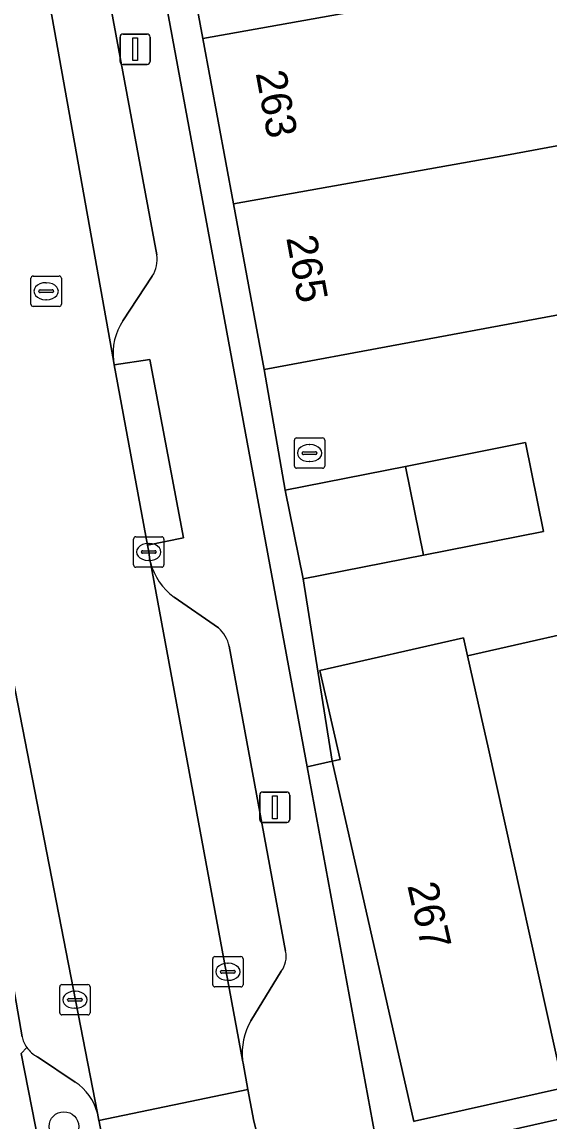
# Model space of a CAD drawing. Extents: x 160377 to 161131, y 383938 to 384853.
# Drawn here: x 160815.54 to 160832.91, y 384537.03 to 384573.2 of the extents above; entities that cross this region are included whole.
import ezdxf

# ---------------------------------------------------------------- set-up
doc = ezdxf.new("R2010")
doc.units = 0
for name, color, linetype in [('IMGEO_Boom', 7, 'Continuous'), ('IMGEO_Erf', 7, 'Continuous'), ('IMGEO_Groenvoorziening', 7, 'Continuous'), ('IMGEO_Kolk', 7, 'Continuous'), ('IMGEO_Lichtmast', 7, 'Continuous'), ('IMGEO_Muur', 7, 'Continuous'), ('IMGEO_Pand', 7, 'Continuous'), ('IMGEO_Pand_nummerreeks', 7, 'Continuous'), ('IMGEO_Parkeervlak_open', 7, 'Continuous'), ('IMGEO_Rijbaan_lokaal_open', 7, 'Continuous'), ('IMGEO_Rioolput', 7, 'Continuous'), ('IMGEO_Voetpad_open', 7, 'Continuous')]:
    doc.layers.add(name, color=color, linetype=linetype)

msp = doc.modelspace()

# ---------------------------------------------------------------- linework, layer by layer
at = {"layer": 'IMGEO_Boom'}
msp.add_circle((160816.923, 384536.878), 0.489, dxfattribs=at)
at = {"layer": 'IMGEO_Erf'}
for points in [[(160836.079, 384564.109), (160832.472, 384563.442), (160823.508, 384561.776), (160824.197, 384557.807), (160828.153, 384558.589), (160832.1, 384559.368), (160832.697, 384556.45), (160828.75, 384555.671), (160824.794, 384554.889), (160825.745, 384548.894), (160824.919, 384548.707), (160827.304, 384535.796), (160828.384, 384536.039), (160877.181, 384547.027)], [(160833.346, 384538.155), (160828.447, 384537.052), (160828.43, 384537.048), (160825.745, 384548.894), (160826.001, 384548.952), (160825.337, 384551.881), (160830.056, 384552.951), (160830.191, 384552.359), (160835.314, 384553.515)]]:
    msp.add_lwpolyline(points, dxfattribs=at)
at = {"layer": 'IMGEO_Groenvoorziening'}
for points in [[(160815.7, 384539.483), (160815.52, 384539.282), (160816.219, 384535.713), (160818.259, 384536.105), (160818.077, 384537.048), (160818.072, 384537.074), (160818.024, 384537.321)], [(160817.288, 384538.344), (160816.055, 384539.17)]]:
    msp.add_lwpolyline(points, dxfattribs=at)
for centre, radius, start, end in [((160816.519, 384540.054), 0.998, 214.8819, 242.3135), ((160816.274, 384536.838), 1.816, 15.4246, 56.0419)]:
    msp.add_arc(centre, radius, start, end, dxfattribs=at)
at = {"layer": 'IMGEO_Kolk'}
for p, q in [((160819.211, 384555.347), (160819.211, 384556.199)), ((160819.286, 384556.273), (160820.138, 384556.273)), ((160820.212, 384556.199), (160820.212, 384555.347)), ((160819.47, 384555.767), (160819.47, 384555.779)), ((160819.513, 384555.816), (160819.911, 384555.816)), ((160819.699, 384556.053), (160819.724, 384556.053)), ((160819.954, 384555.779), (160819.954, 384555.767)), ((160819.908, 384555.73), (160819.51, 384555.73)), ((160819.722, 384555.493), (160819.697, 384555.493)), ((160820.138, 384555.273), (160819.286, 384555.273)), ((160821.814, 384541.543), (160821.814, 384542.395)), ((160821.889, 384542.469), (160822.741, 384542.469)), ((160822.815, 384542.395), (160822.815, 384541.543)), ((160822.116, 384542.012), (160822.514, 384542.012)), ((160822.302, 384542.249), (160822.327, 384542.249)), ((160822.073, 384541.963), (160822.073, 384541.975)), ((160822.511, 384541.926), (160822.113, 384541.926)), ((160822.325, 384541.689), (160822.3, 384541.689)), ((160822.557, 384541.975), (160822.557, 384541.963)), ((160816.784, 384540.623), (160816.784, 384541.475)), ((160816.859, 384541.549), (160817.711, 384541.549)), ((160817.272, 384541.329), (160817.297, 384541.329)), ((160817.785, 384541.475), (160817.785, 384540.623)), ((160822.741, 384541.469), (160821.889, 384541.469)), ((160817.043, 384541.043), (160817.043, 384541.055)), ((160817.481, 384541.006), (160817.083, 384541.006)), ((160817.086, 384541.092), (160817.484, 384541.092)), ((160817.527, 384541.055), (160817.527, 384541.043)), ((160817.295, 384540.769), (160817.27, 384540.769)), ((160817.711, 384540.549), (160816.859, 384540.549))]:
    msp.add_line(p, q, dxfattribs=at)
for points in [[(160819.211, 384555.347), (160819.211, 384556.199)], [(160819.286, 384556.273), (160820.138, 384556.273)], [(160820.212, 384556.199), (160820.212, 384555.347)], [(160820.138, 384555.273), (160819.286, 384555.273)], [(160821.814, 384541.543), (160821.814, 384542.395)], [(160821.889, 384542.469), (160822.741, 384542.469)], [(160822.815, 384542.395), (160822.815, 384541.543)], [(160816.784, 384540.623), (160816.784, 384541.475)], [(160816.859, 384541.549), (160817.711, 384541.549)], [(160817.785, 384541.475), (160817.785, 384540.623)], [(160822.741, 384541.469), (160821.889, 384541.469)], [(160817.711, 384540.549), (160816.859, 384540.549)]]:
    msp.add_lwpolyline(points, dxfattribs=at)
for centre, radius, start, end in [((160819.288, 384556.197), 0.0765, 91.552, 178.448), ((160819.288, 384556.197), 0.0765, 91.552, 178.448), ((160820.136, 384556.197), 0.0765, 1.552, 88.448), ((160820.136, 384556.197), 0.0765, 1.552, 88.448), ((160819.51, 384555.776), 0.0403, 85.8775, 175.7526), ((160819.507, 384555.766), 0.0366, 178.938, 274.7102), ((160819.911, 384555.773), 0.043, 264.8664, 352.4533), ((160819.915, 384555.778), 0.0386, 1.7309, 96.639), ((160819.288, 384555.349), 0.0765, 181.552, 268.448), ((160819.288, 384555.349), 0.0765, 181.552, 268.448), ((160820.136, 384555.349), 0.0765, 271.552, 358.448), ((160820.136, 384555.349), 0.0765, 271.552, 358.448), ((160821.891, 384542.393), 0.0765, 91.552, 178.448), ((160821.891, 384542.393), 0.0765, 91.552, 178.448), ((160822.739, 384542.393), 0.0765, 1.552, 88.448), ((160822.739, 384542.393), 0.0765, 1.552, 88.448), ((160822.113, 384541.972), 0.0403, 85.8775, 175.7526), ((160822.518, 384541.974), 0.0386, 1.7309, 96.639), ((160822.11, 384541.962), 0.0366, 178.938, 274.7102), ((160822.514, 384541.969), 0.043, 264.8664, 352.4533), ((160816.861, 384541.473), 0.0765, 91.552, 178.448), ((160816.861, 384541.473), 0.0765, 91.552, 178.448), ((160817.709, 384541.473), 0.0765, 1.552, 88.448), ((160817.709, 384541.473), 0.0765, 1.552, 88.448), ((160821.891, 384541.545), 0.0765, 181.552, 268.448), ((160821.891, 384541.545), 0.0765, 181.552, 268.448), ((160822.739, 384541.545), 0.0765, 271.552, 358.448), ((160822.739, 384541.545), 0.0765, 271.552, 358.448), ((160817.083, 384541.052), 0.0403, 85.8775, 175.7526), ((160817.08, 384541.042), 0.0366, 178.938, 274.7102), ((160817.484, 384541.049), 0.043, 264.8664, 352.4533), ((160817.488, 384541.054), 0.0386, 1.7309, 96.639), ((160816.861, 384540.625), 0.0765, 181.552, 268.448), ((160816.861, 384540.625), 0.0765, 181.552, 268.448), ((160817.709, 384540.625), 0.0765, 271.552, 358.448), ((160817.709, 384540.625), 0.0765, 271.552, 358.448)]:
    msp.add_arc(centre, radius, start, end, dxfattribs=at)
for centre, major_axis, ratio, start_param, end_param in [((160819.698, 384555.773), (-0.387, 0.002), 0.722429, 4.712389, 7.853982), ((160819.723, 384555.773), (-0.39, 0.002), 0.717154, 1.570796, 4.712389), ((160822.301, 384541.969), (-0.387, 0.002), 0.722429, 4.712389, 7.853982), ((160822.326, 384541.969), (-0.39, 0.002), 0.717154, 1.570796, 4.712389), ((160817.271, 384541.049), (-0.387, 0.002), 0.722429, 4.712389, 7.853982), ((160817.296, 384541.049), (-0.39, 0.002), 0.717154, 1.570796, 4.712389)]:
    msp.add_ellipse(centre, major_axis=major_axis, ratio=ratio, start_param=start_param, end_param=end_param, dxfattribs=at)
at = {"layer": 'IMGEO_Lichtmast'}
for p, q in [((160818.867, 384572.805), (160819.657, 384572.805)), ((160819.657, 384572.805), (160818.867, 384572.805)), ((160818.767, 384571.905), (160818.767, 384572.705)), ((160818.767, 384572.705), (160818.767, 384571.905)), ((160819.757, 384572.705), (160819.757, 384571.905)), ((160819.757, 384571.905), (160819.757, 384572.705)), ((160819.657, 384571.805), (160818.867, 384571.805)), ((160818.867, 384571.805), (160819.657, 384571.805)), ((160823.459, 384547.878), (160824.249, 384547.878)), ((160824.249, 384547.878), (160823.459, 384547.878)), ((160823.359, 384546.978), (160823.359, 384547.778)), ((160823.359, 384547.778), (160823.359, 384546.978)), ((160824.349, 384547.778), (160824.349, 384546.978)), ((160824.349, 384546.978), (160824.349, 384547.778)), ((160824.249, 384546.878), (160823.459, 384546.878)), ((160823.459, 384546.878), (160824.249, 384546.878))]:
    msp.add_line(p, q, dxfattribs=at)
for points in [[(160819.187, 384572.68), (160819.337, 384572.68), (160819.337, 384571.93), (160819.187, 384571.93), (160819.187, 384572.68)], [(160823.779, 384547.753), (160823.929, 384547.753), (160823.929, 384547.003), (160823.779, 384547.003), (160823.779, 384547.753)]]:
    msp.add_lwpolyline(points, dxfattribs=at)
for centre, start, end in [((160818.867, 384572.705), 90, 180), ((160818.867, 384572.705), 90, 180), ((160819.657, 384572.705), 0, 90), ((160819.657, 384572.705), 360, 90), ((160818.867, 384571.905), 180, 270), ((160818.867, 384571.905), 180, 270), ((160819.657, 384571.905), 270, 0), ((160819.657, 384571.905), 270, 0), ((160823.459, 384547.778), 90, 180), ((160823.459, 384547.778), 90, 180), ((160824.249, 384547.778), 0, 90), ((160824.249, 384547.778), 360, 90), ((160823.459, 384546.978), 180, 270), ((160823.459, 384546.978), 180, 270), ((160824.249, 384546.978), 270, 0), ((160824.249, 384546.978), 270, 0)]:
    msp.add_arc(centre, 0.1, start, end, dxfattribs=at)
at = {"layer": 'IMGEO_Muur'}
msp.add_lwpolyline([(160825.745, 384548.894), (160824.794, 384554.889)], dxfattribs=at)
at = {"layer": 'IMGEO_Pand'}
for points in [[(160829.466, 384579.707), (160820.48, 384578.095), (160821.489, 384572.655), (160830.472, 384574.267), (160834.079, 384574.933), (160833.073, 384580.374)], [(160834.079, 384574.933), (160830.472, 384574.267), (160821.489, 384572.655), (160822.498, 384567.216), (160831.477, 384568.826), (160835.084, 384569.493)], [(160835.084, 384569.493), (160831.477, 384568.826), (160822.498, 384567.216), (160823.508, 384561.776), (160832.472, 384563.442), (160836.079, 384564.109)], [(160832.1, 384559.368), (160828.153, 384558.589), (160828.75, 384555.671), (160832.697, 384556.45)], [(160828.153, 384558.589), (160824.197, 384557.807), (160824.794, 384554.889), (160828.75, 384555.671)], [(160835.981, 384550.558), (160835.314, 384553.515), (160830.191, 384552.359), (160830.718, 384550.022), (160830.858, 384549.402), (160833.346, 384538.155), (160838.47, 384539.309)], [(160830.858, 384549.402), (160830.718, 384550.022), (160830.191, 384552.359), (160830.056, 384552.951), (160825.337, 384551.881), (160826.001, 384548.952), (160825.745, 384548.894), (160828.43, 384537.048), (160828.447, 384537.052), (160833.346, 384538.155)]]:
    msp.add_lwpolyline(points, close=True, dxfattribs=at)
at = {"layer": 'IMGEO_Parkeervlak_open'}
for points in [[(160818.024, 384537.321), (160808.395, 384586.778)], [(160814.28, 384585.825), (160814.64, 384583.89), (160818.551, 384562.065)], [(160807.162, 384583.224), (160808.442, 384576.668), (160809.961, 384576.919), (160810.2, 384575.304), (160808.747, 384575.103), (160810.749, 384564.848), (160812.277, 384565.101), (160812.623, 384563.321), (160811.098, 384563.058), (160813.217, 384552.203), (160814.725, 384552.401), (160814.98, 384550.736), (160813.547, 384550.512), (160814.928, 384543.438), (160815.544, 384539.832)], [(160819.973, 384565.541), (160816.904, 384582.075)], [(160818.864, 384563.369), (160819.829, 384564.845)], [(160819.766, 384555.429), (160822.798, 384539.063)], [(160822, 384553.274), (160820.548, 384554.291)], [(160824.212, 384542.646), (160822.361, 384552.671)], [(160823.067, 384540.361), (160824.07, 384541.984)], [(160816.055, 384539.17), (160817.288, 384538.344)]]:
    msp.add_lwpolyline(points, dxfattribs=at)
for centre, radius, start, end in [((160818.988, 384565.382), 0.998, 327.4479, 9.1734), ((160820.446, 384562.3), 1.909, 145.94, 187.0652), ((160821.746, 384555.952), 2.048, 194.7949, 234.1965), ((160821.277, 384552.432), 1.11, 12.4456, 49.3701), ((160823.407, 384542.472), 0.823, 323.611, 12.1759), ((160824.908, 384539.303), 2.123, 150.1032, 186.4801), ((160816.511, 384540.055), 0.992, 192.9797, 215.1888), ((160816.519, 384540.054), 0.998, 214.8819, 242.3135), ((160816.274, 384536.838), 1.816, 15.4246, 56.0419)]:
    msp.add_arc(centre, radius, start, end, dxfattribs=at)
at = {"layer": 'IMGEO_Rijbaan_lokaal_open'}
for points in [[(160808.366, 384586.942), (160808.395, 384586.778), (160818.024, 384537.321), (160818.072, 384537.074), (160822.974, 384538.097), (160822.812, 384538.963), (160822.804, 384539.013), (160822.798, 384539.063), (160819.766, 384555.429), (160819.757, 384555.467), (160819.748, 384555.505), (160819.712, 384555.773), (160819.668, 384555.994), (160818.573, 384561.931), (160818.551, 384562.065), (160814.64, 384583.89)], [(160823.391, 384536.192), (160823.17, 384537.054), (160822.974, 384538.097), (160818.072, 384537.074), (160818.077, 384537.048), (160818.259, 384536.105), (160818.27, 384536.051), (160818.393, 384535.428)]]:
    msp.add_lwpolyline(points, dxfattribs=at)
at = {"layer": 'IMGEO_Rioolput'}
for p, q in [((160815.913, 384564.848), (160816.765, 384564.848)), ((160815.838, 384563.922), (160815.838, 384564.774)), ((160816.326, 384564.628), (160816.351, 384564.628)), ((160816.839, 384564.774), (160816.839, 384563.922)), ((160816.097, 384564.342), (160816.097, 384564.354)), ((160816.535, 384564.305), (160816.137, 384564.305)), ((160816.14, 384564.391), (160816.538, 384564.391)), ((160816.581, 384564.354), (160816.581, 384564.342)), ((160816.765, 384563.848), (160815.913, 384563.848)), ((160816.349, 384564.068), (160816.324, 384564.068)), ((160824.499, 384558.599), (160824.499, 384559.451)), ((160824.574, 384559.525), (160825.426, 384559.525)), ((160825.5, 384559.451), (160825.5, 384558.599)), ((160824.758, 384559.019), (160824.758, 384559.031)), ((160824.801, 384559.068), (160825.199, 384559.068)), ((160824.987, 384559.305), (160825.012, 384559.305)), ((160825.242, 384559.031), (160825.242, 384559.019)), ((160825.196, 384558.982), (160824.798, 384558.982)), ((160825.01, 384558.745), (160824.985, 384558.745)), ((160825.426, 384558.525), (160824.574, 384558.525))]:
    msp.add_line(p, q, dxfattribs=at)
for points in [[(160815.913, 384564.848), (160816.765, 384564.848)], [(160815.838, 384563.922), (160815.838, 384564.774)], [(160816.839, 384564.774), (160816.839, 384563.922)], [(160816.765, 384563.848), (160815.913, 384563.848)], [(160824.499, 384558.599), (160824.499, 384559.451)], [(160824.574, 384559.525), (160825.426, 384559.525)], [(160825.5, 384559.451), (160825.5, 384558.599)], [(160825.426, 384558.525), (160824.574, 384558.525)]]:
    msp.add_lwpolyline(points, dxfattribs=at)
for centre, radius, start, end in [((160815.915, 384564.772), 0.0765, 91.552, 178.448), ((160815.915, 384564.772), 0.0765, 91.552, 178.448), ((160816.763, 384564.772), 0.0765, 1.552, 88.448), ((160816.763, 384564.772), 0.0765, 1.552, 88.448), ((160816.137, 384564.351), 0.0403, 85.8775, 175.7526), ((160816.134, 384564.341), 0.0366, 178.938, 274.7102), ((160816.538, 384564.348), 0.043, 264.8664, 352.4533), ((160816.542, 384564.353), 0.0386, 1.7309, 96.639), ((160815.915, 384563.924), 0.0765, 181.552, 268.448), ((160815.915, 384563.924), 0.0765, 181.552, 268.448), ((160816.763, 384563.924), 0.0765, 271.552, 358.448), ((160816.763, 384563.924), 0.0765, 271.552, 358.448), ((160824.576, 384559.449), 0.0765, 91.552, 178.448), ((160824.576, 384559.449), 0.0765, 91.552, 178.448), ((160825.424, 384559.449), 0.0765, 1.552, 88.448), ((160825.424, 384559.449), 0.0765, 1.552, 88.448), ((160824.798, 384559.028), 0.0403, 85.8775, 175.7526), ((160824.795, 384559.018), 0.0366, 178.938, 274.7102), ((160825.199, 384559.025), 0.043, 264.8664, 352.4533), ((160825.203, 384559.03), 0.0386, 1.7309, 96.639), ((160824.576, 384558.601), 0.0765, 181.552, 268.448), ((160824.576, 384558.601), 0.0765, 181.552, 268.448), ((160825.424, 384558.601), 0.0765, 271.552, 358.448), ((160825.424, 384558.601), 0.0765, 271.552, 358.448)]:
    msp.add_arc(centre, radius, start, end, dxfattribs=at)
for centre, major_axis, ratio, start_param, end_param in [((160816.325, 384564.348), (-0.387, 0.002), 0.722429, 4.712389, 7.853982), ((160816.35, 384564.348), (-0.39, 0.002), 0.717154, 1.570796, 4.712389), ((160824.986, 384559.025), (-0.387, 0.002), 0.722429, 4.712389, 7.853982), ((160825.011, 384559.025), (-0.39, 0.002), 0.717154, 1.570796, 4.712389)]:
    msp.add_ellipse(centre, major_axis=major_axis, ratio=ratio, start_param=start_param, end_param=end_param, dxfattribs=at)
at = {"layer": 'IMGEO_Voetpad_open'}
for points in [[(160750.44, 384669.667), (160816.984, 384591.607), (160818.812, 384581.761), (160824.919, 384548.707), (160825.745, 384548.894), (160824.794, 384554.889), (160824.197, 384557.807), (160823.508, 384561.776), (160822.498, 384567.216), (160821.489, 384572.655), (160820.48, 384578.095), (160819.47, 384583.535), (160818.461, 384588.975), (160817.887, 384592.065), (160816.799, 384593.342), (160813.196, 384597.57), (160809.528, 384601.874), (160805.909, 384606.122), (160802.399, 384610.25), (160798.948, 384614.297), (160795.497, 384618.345)], [(160745.948, 384658.713), (160745.656, 384658.636), (160741.646, 384663.363), (160743.2, 384664.676), (160741.8, 384666.319), (160738.611, 384663.488), (160752.089, 384647.71), (160753.096, 384646.531), (160756.612, 384642.415), (160759.221, 384639.361), (160784.593, 384609.659), (160785.555, 384608.533), (160801.827, 384589.484), (160804.227, 384586.696), (160805.221, 384581.626), (160814.707, 384533.039), (160818.393, 384535.428), (160818.27, 384536.051), (160818.259, 384536.105), (160816.219, 384535.713), (160815.52, 384539.282), (160815.7, 384539.483)], [(160816.147, 384586.236), (160816.904, 384582.075), (160819.973, 384565.541)], [(160815.544, 384539.832), (160814.928, 384543.438), (160813.547, 384550.512), (160813.217, 384552.203), (160811.098, 384563.058), (160810.749, 384564.848), (160808.747, 384575.103), (160808.442, 384576.668), (160807.162, 384583.224)], [(160822.798, 384539.063), (160822.804, 384539.013), (160822.812, 384538.963), (160822.974, 384538.097), (160823.17, 384537.054), (160823.391, 384536.192), (160827.304, 384535.796), (160824.919, 384548.707), (160818.812, 384581.761)], [(160819.829, 384564.845), (160818.864, 384563.369)], [(160818.551, 384562.065), (160818.573, 384561.931), (160819.747, 384562.108), (160820.851, 384556.238), (160819.668, 384555.994), (160819.712, 384555.773), (160819.748, 384555.505), (160819.757, 384555.467), (160819.766, 384555.429)], [(160935.073, 384557.207), (160934.119, 384558.397), (160932.131, 384556.814), (160932.313, 384556.509), (160931.962, 384556.425), (160931.143, 384557.427), (160925.7, 384555.846), (160923.778, 384555.265), (160920.05, 384554.138), (160919.688, 384554.028), (160916.6, 384553.146), (160916.499, 384553.113), (160909.96, 384550.971), (160903.215, 384548.761), (160902.031, 384552.528), (160890.799, 384550.034), (160877.181, 384547.027), (160828.384, 384536.039), (160827.304, 384535.796), (160823.391, 384536.192)], [(160820.548, 384554.291), (160822, 384553.274)], [(160822.361, 384552.671), (160824.212, 384542.646)], [(160824.07, 384541.984), (160823.067, 384540.361)]]:
    msp.add_lwpolyline(points, dxfattribs=at)
msp.add_lwpolyline([(160818.573, 384561.931), (160819.668, 384555.994), (160820.851, 384556.238), (160819.747, 384562.108)], close=True, dxfattribs=at)
for centre, radius, start, end in [((160818.988, 384565.382), 0.998, 327.4479, 9.1734), ((160820.446, 384562.3), 1.909, 145.94, 187.0652), ((160821.746, 384555.952), 2.048, 194.7949, 234.1965), ((160821.277, 384552.432), 1.11, 12.4456, 49.3701), ((160823.407, 384542.472), 0.823, 323.611, 12.1759), ((160824.908, 384539.303), 2.123, 150.1032, 186.4801), ((160816.511, 384540.055), 0.992, 192.9797, 215.1888)]:
    msp.add_arc(centre, radius, start, end, dxfattribs=at)

# ---------------------------------------------------------------- texts
at = {"layer": 'IMGEO_Pand_nummerreeks'}
for s, rotation, p in [('263', 280.5136, (160823.225, 384571.52)), ('265', 280.5136, (160824.23, 384566.103)), ('267', 282.771, (160828.21, 384544.805))]:
    msp.add_text(s, height=1, rotation=rotation, dxfattribs=at).set_placement(p)

doc.saveas('drawing.dxf')
